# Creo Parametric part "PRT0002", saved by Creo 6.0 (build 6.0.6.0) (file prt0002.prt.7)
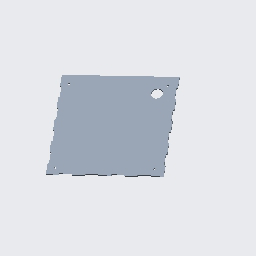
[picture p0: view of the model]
Units: Inch lbm Second (Pro/E Default); INCH, POUND, SECS

Created from: INLBS_PART_SOLID.PRT

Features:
  1. datum plane "RIGHT"
  2. datum plane "TOP"
  3. datum plane "FRONT"
  4. coordinate system
  5. sketch "Sketch 1"
  6. extrusion "Extrude 1"
  7. sketch "Sketch 2"
  8. extruded cut "Extrude 2"
  9. sketch "Sketch 3"
  10. sketch "Sketch 4"
  11. extruded cut "Extrude 3"

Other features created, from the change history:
  extruded cut "Extrude 3"
  sketch "Sketch 4"

Surfaces: 54 plane, 5 cylinder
